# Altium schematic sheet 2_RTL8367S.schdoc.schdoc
size 431 x 309 mm; Symbol: Sheet-Symbol_A3; Device: Sheet-Symbol_A3; Company: 嘉立创EDA; Version: V1.0; Page Size: A3; @Project Name: RTL8367S_RTL8213B; @Page Count: 5; @Update Date: 2022-12-07; @Create Date: 2022-10-17; @Schematic Name: Schematic1; @Page No: 2; @Page Name: RTL8367S
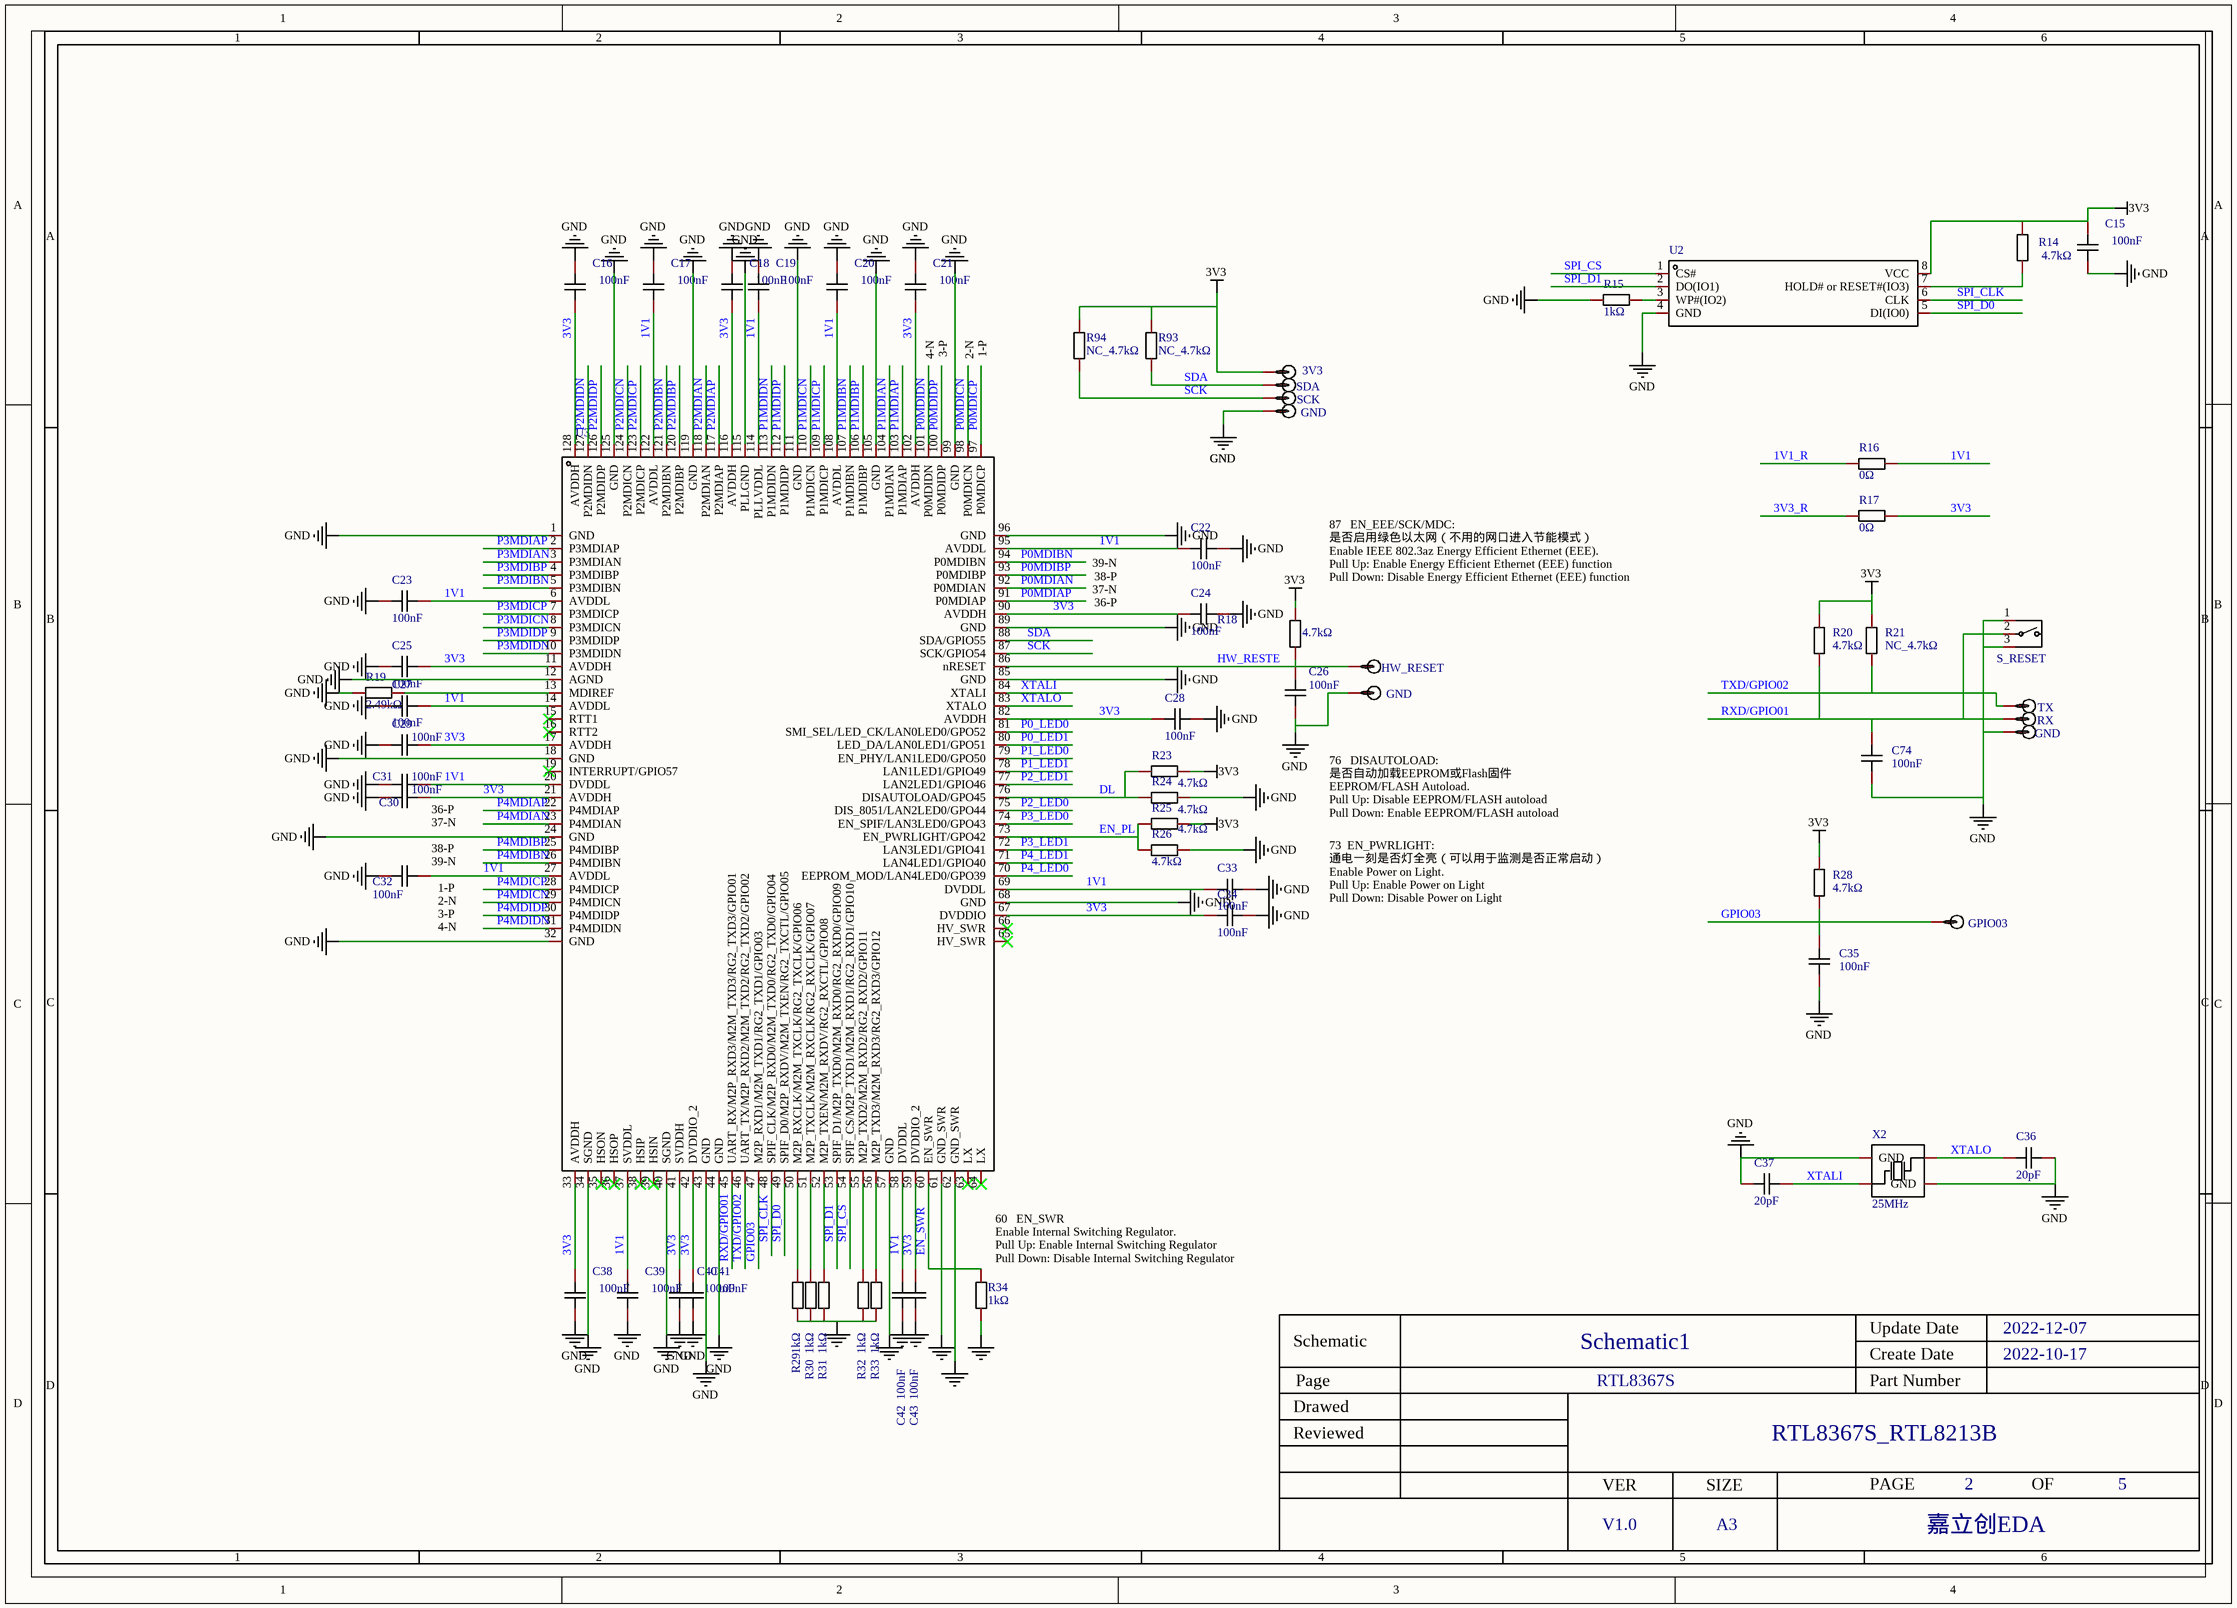
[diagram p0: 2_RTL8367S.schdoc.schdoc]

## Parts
(Parts that share a designator on the sheet are numbered #1, #2 ... from top to bottom, then left to right.)
3V3  测试点  [TP-1.5MM]  (value not drawn)
C15  value 100nF  [C0402_NEW]  (hidden comment: CL05B104KO5NNNC)
C16  value 100nF  [C0402_NEW]  (hidden comment: CL05B104KO5NNNC)
C17  value 100nF  [C0402_NEW]  (hidden comment: CL05B104KO5NNNC)
C18  value 100nF  [C0402_NEW]  (hidden comment: CL05B104KO5NNNC)
C19  value 100nF  [C0402_NEW]  (hidden comment: CL05B104KO5NNNC)
C20  value 100nF  [C0402_NEW]  (hidden comment: CL05B104KO5NNNC)
C21  value 100nF  [C0402_NEW]  (hidden comment: CL05B104KO5NNNC)
C22  value 100nF  [C0402_NEW]  (hidden comment: CL05B104KO5NNNC)
C23  value 100nF  [C0402_NEW]  (hidden comment: CL05B104KO5NNNC)
C24  value 100nF  [C0402_NEW]  (hidden comment: CL05B104KO5NNNC)
C25  value 100nF  [C0402_NEW]  (hidden comment: CL05B104KO5NNNC)
C26  value 100nF  [C0402_NEW]  (hidden comment: CL05B104KO5NNNC)
C27  value 100nF  [C0402_NEW]  (hidden comment: CL05B104KO5NNNC)
C28  value 100nF  [C0402_NEW]  (hidden comment: CL05B104KO5NNNC)
C29  value 100nF  [C0402_NEW]  (hidden comment: CL05B104KO5NNNC)
C30  value 100nF  [C0402_NEW]  (hidden comment: CL05B104KO5NNNC)
C31  value 100nF  [C0402_NEW]  (hidden comment: CL05B104KO5NNNC)
C32  value 100nF  [C0402_NEW]  (hidden comment: CL05B104KO5NNNC)
C33  value 100nF  [C0402_NEW]  (hidden comment: CL05B104KO5NNNC)
C34  value 100nF  [C0402_NEW]  (hidden comment: CL05B104KO5NNNC)
C35  value 100nF  [C0402_NEW]  (hidden comment: CL05B104KO5NNNC)
C36  value 20pF  [C0402]  (hidden comment: 0402CG200J500NT)
C37  value 20pF  [C0402]  (hidden comment: 0402CG200J500NT)
C38  value 100nF  [C0402_NEW]  (hidden comment: CL05B104KO5NNNC)
C39  value 100nF  [C0402_NEW]  (hidden comment: CL05B104KO5NNNC)
C40  value 100nF  [C0402_NEW]  (hidden comment: CL05B104KO5NNNC)
C41  value 100nF  [C0402_NEW]  (hidden comment: CL05B104KO5NNNC)
C42  value 100nF  [C0402_NEW]  (hidden comment: CL05B104KO5NNNC)
C43  value 100nF  [C0402_NEW]  (hidden comment: CL05B104KO5NNNC)
C74  value 100nF  [C0402_NEW]  (hidden comment: CL05B104KO5NNNC)
GND#1  测试点  [TP-1.5MM]  (value not drawn)
GND#2  测试点  [TP-1.5MM]  (value not drawn)
GND#3  测试点  [TP-1.5MM]  (value not drawn)
GPIO03  测试点  [TP-1.5MM]  (value not drawn)
HW_RESET  测试点  [TP-1.5MM]  (value not drawn)
R14  value 4.7kΩ  [R0402]  (hidden comment: 0402WGF4701TCE)
R15  value 1kΩ  [R0402]  (hidden comment: 0402WGF1001TCE)
R16  value 0Ω  [R0603]  (hidden comment: 0603WAF0000T5E)
R17  value 0Ω  [R0603]  (hidden comment: 0603WAF0000T5E)
R18  value 4.7kΩ  [R0402]  (hidden comment: 0402WGF4701TCE)
R19  value 2.49kΩ  [R0402]  (hidden comment: RC0402FR-072K49L)
R20  value 4.7kΩ  [R0402]  (hidden comment: 0402WGF4701TCE)
R21  value NC_4.7kΩ  [R0402]  (hidden comment: 0402WGF4701TCE)
R23  4.7kΩ  [R0402]
R24  value 4.7kΩ  [r0402]  (hidden comment: tr0402d10k0q1025z)
R25  4.7kΩ  [R0402]
R26  value 4.7kΩ  [r0402]  (hidden comment: tr0402d10k0q1025z)
R28  value 4.7kΩ  [R0402]  (hidden comment: 0402WGF4701TCE)
R29  value 1kΩ  [R0402]  (hidden comment: 0402WGF1001TCE)
R30  value 1kΩ  [R0402]  (hidden comment: 0402WGF1001TCE)
R31  value 1kΩ  [R0402]  (hidden comment: 0402WGF1001TCE)
R32  value 1kΩ  [R0402]  (hidden comment: 0402WGF1001TCE)
R33  value 1kΩ  [R0402]  (hidden comment: 0402WGF1001TCE)
R34  value 1kΩ  [R0402]  (hidden comment: 0402WGF1001TCE)
R93  value NC_4.7kΩ  [R0402]  (hidden comment: 0402WGF4701TCE)
R94  value NC_4.7kΩ  [R0402]  (hidden comment: 0402WGF4701TCE)
RX  测试点  [TP-1.5MM]  (value not drawn)
S_RESET  st-1133  [key-smd_st-1133]  (value not drawn)
SCK  测试点  [TP-1.5MM]  (value not drawn)
SDA  测试点  [TP-1.5MM]  (value not drawn)
TX  测试点  [TP-1.5MM]  (value not drawn)
U2  w25q32jvssiq  [soic-8_l5.3-w5.3-p1.27-ls8.0-bl]  (value not drawn)
U3  RTL8367S-CG  [LQFP-128_L14.0-W14.0-P0.40-LS16.0-BL]  (value not drawn)
X2  value 25MHz  [OSC-SMD_4P-L3.2-W2.5-BL]  (hidden comment: X322525MOB4SI)

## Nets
3V3: 3V3.1 C15.2 C16.1 C18.1 C21.1 C24.2 C25.2 C28.1 C29.2 C30.2 C34.1 C38.2 C40.2 C41.2 C43.2 R14.2 R17.2 R18.2 R20.2 R21.1 R23.2 R25.2 R28.2 R93.2 R94.2 U2.8(VCC) U3.11(AVDDH) U3.17(AVDDH) U3.21(AVDDH) U3.33(AVDDH) U3.41(SVDDH) U3.42(DVDDIO_2) U3.59(DVDDIO_2) U3.67(DVDDIO) U3.82(AVDDH) U3.90(AVDDH) U3.102(AVDDH) U3.116(AVDDH) U3.128(AVDDH)
GND: C15.1 C16.2 C17.2 C18.2 C19.2 C20.2 C21.2 C22.1 C23.1 C24.1 C25.1 C26.1 C27.1 C28.2 C29.1 C30.1 C31.1 C32.1 C33.2 C34.2 C35.1 C36.2 C37.1 C38.1 C39.1 C40.1 C41.1 C42.1 C43.1 C74.1 GND#1.1 GND#2.1 GND#3.1 R15.1 R19.1 R24.2 R26.2 R29.1 R30.1 R31.1 R32.1 R33.1 R34.1 S_RESET.1 S_RESET.3 U2.4(GND) U3.1(GND) U3.12(AGND) U3.18(GND) U3.24(GND) U3.32(GND) U3.34(SGND) U3.40(SGND) U3.43(GND) U3.44(GND) U3.57(GND) U3.61(GND_SWR) U3.62(GND_SWR) U3.68(GND) U3.85(GND) U3.89(GND) U3.96(GND) U3.99(GND) U3.105(GND) U3.111(GND) U3.115(PLLGND) U3.119(GND) U3.125(GND) X2.2(GND) X2.4(GND)
1V1: C17.1 C19.1 C20.1 C22.2 C23.2 C27.2 C31.2 C32.2 C33.1 C39.2 C42.2 R16.2 U3.6(AVDDL) U3.14(AVDDL) U3.20(DVDDL) U3.27(AVDDL) U3.37(SVDDL) U3.58(DVDDL) U3.69(DVDDL) U3.95(AVDDL) U3.108(AVDDL) U3.114(PLLVDDL) U3.122(AVDDL)
1V1_R: R16.1
3V3_R: R17.1
DL: R23.1 R24.1 U3.76(DISAUTOLOAD/GPO45)
EN_PL: R25.1 R26.1 U3.73(EN_PWRLIGHT/GPO42)
EN_SWR: R34.2 U3.60(EN_SWR)
GPIO03: C35.2 GPIO03.1 R28.1 U3.47(M2P_RXD1/M2M_TXD1/RG2_TXD1/GPIO03)
HW_RESTE: C26.2 HW_RESET.1 R18.1 U3.86(nRESET)
P0_LED0: U3.81(SMI_SEL/LED_CK/LAN0LED0/GPO52)
P0_LED1: U3.80(LED_DA/LAN0LED1/GPO51)
P0MDIAN: U3.92(P0MDIAN)
P0MDIAP: U3.91(P0MDIAP)
P0MDIBN: U3.94(P0MDIBN)
P0MDIBP: U3.93(P0MDIBP)
P0MDICN: U3.98(P0MDICN)
P0MDICP: U3.97(P0MDICP)
P0MDIDN: U3.101(P0MDIDN)
P0MDIDP: U3.100(P0MDIDP)
P1_LED0: U3.79(EN_PHY/LAN1LED0/GPO50)
P1_LED1: U3.78(LAN1LED1/GPIO49)
P1MDIAN: U3.104(P1MDIAN)
P1MDIAP: U3.103(P1MDIAP)
P1MDIBN: U3.107(P1MDIBN)
P1MDIBP: U3.106(P1MDIBP)
P1MDICN: U3.110(P1MDICN)
P1MDICP: U3.109(P1MDICP)
P1MDIDN: U3.113(P1MDIDN)
P1MDIDP: U3.112(P1MDIDP)
P2_LED0: U3.75(DIS_8051/LAN2LED0/GPO44)
P2_LED1: U3.77(LAN2LED1/GPIO46)
P2MDIAN: U3.118(P2MDIAN)
P2MDIAP: U3.117(P2MDIAP)
P2MDIBN: U3.121(P2MDIBN)
P2MDIBP: U3.120(P2MDIBP)
P2MDICN: U3.124(P2MDICN)
P2MDICP: U3.123(P2MDICP)
P2MDIDN: U3.127(P2MDIDN)
P2MDIDP: U3.126(P2MDIDP)
P3_LED0: U3.74(EN_SPIF/LAN3LED0/GPO43)
P3_LED1: U3.72(LAN3LED1/GPIO41)
P3MDIAN: U3.3(P3MDIAN)
P3MDIAP: U3.2(P3MDIAP)
P3MDIBN: U3.5(P3MDIBN)
P3MDIBP: U3.4(P3MDIBP)
P3MDICN: U3.8(P3MDICN)
P3MDICP: U3.7(P3MDICP)
P3MDIDN: U3.10(P3MDIDN)
P3MDIDP: U3.9(P3MDIDP)
P4_LED0: U3.70(EEPROM_MOD/LAN4LED0/GPO39)
P4_LED1: U3.71(LAN4LED1/GPIO40)
P4MDIAN: U3.23(P4MDIAN)
P4MDIAP: U3.22(P4MDIAP)
P4MDIBN: U3.26(P4MDIBN)
P4MDIBP: U3.25(P4MDIBP)
P4MDICN: U3.29(P4MDICN)
P4MDICP: U3.28(P4MDICP)
P4MDIDN: U3.31(P4MDIDN)
P4MDIDP: U3.30(P4MDIDP)
RXD/GPIO01: C74.2 R20.1 RX.1 S_RESET.2 U3.45(UART_RX/M2P_RXD3/M2M_TXD3/RG2_TXD3/GPIO01)
SCK: R94.1 SCK.1 U3.87(SCK/GPIO54)
SDA: R93.1 SDA.1 U3.88(SDA/GPIO55)
SPI_CLK: U2.6(CLK) U3.48(SPIF_CLK/M2P_RXD0/M2M_TXD0/RG2_TXD0/GPIO04)
SPI_CS: U2.1(CS#) U3.54(SPIF_CS/M2P_TXD1/M2M_RXD1/RG2_RXD1/GPIO10)
SPI_D0: U2.5(DI(IO0)) U3.49(SPIF_D0/M2P_RXDV/M2M_TXEN/RG2_TXCTL/GPIO05)
SPI_D1: U2.2(DO(IO1)) U3.53(SPIF_D1/M2P_TXD0/M2M_RXD0/RG2_RXD0/GPIO09)
TXD/GPIO02: R21.2 TX.1 U3.46(UART_TX/M2P_RXD2/M2M_TXD2/RG2_TXD2/GPIO02)
XTALI: C37.2 U3.84(XTALI) X2.1(OSC1)
XTALO: C36.1 U3.83(XTALO) X2.3(OSC2)
NetR14_1: R14.1 U2.7(HOLD#_or_RESET#(IO3))
NetR15_2: R15.2 U2.3(WP#(IO2))
NetR19_2: R19.2 U3.13(MDIREF)
NetR29_2: R29.2 U3.50(M2P_RXCLK/M2M_TXCLK/RG2_TXCLK/GPIO06)
NetR30_2: R30.2 U3.51(M2P_TXCLK/M2M_RXCLK/RG2_RXCLK/GPIO07)
NetR31_2: R31.2 U3.52(M2P_TXEN/M2M_RXDV/RG2_RXCTL/GPIO08)
NetR32_2: R32.2 U3.55(M2P_TXD2/M2M_RXD2/RG2_RXD2/GPIO11)
NetR33_2: R33.2 U3.56(M2P_TXD3/M2M_RXD3/RG2_RXD3/GPIO12)

Not connected (* = marked no-connect by the designer): U3 15(RTT1)* 16(RTT2)* 19(INTERRUPT/GPIO57)* 35(HSON)* 36(HSOP)* 38(HSIP)* 39(HSIN)* 63(LX)* 64(LX)* 65(HV_SWR)* 66(HV_SWR)*

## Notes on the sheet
- (near C21) 4-N
- (near C21) 3-P
- 2-N
- 1-P
- 87   EN_EEE/SCK/MDC:
  是否启用绿色以太网（不用的网口进入节能模式）
  Enable IEEE 802.3az Energy Efficient Ethernet (EEE).
  Pull Up: Enable Energy Efficient Ethernet (EEE) function
  Pull Down: Disable Energy Efficient Ethernet (EEE) function
- 37-N
- 38-P
- 39-N
- 36-P
- 76   DISAUTOLOAD:
  是否自动加载EEPROM或Flash固件
  EEPROM/FLASH Autoload.
  Pull Up: Disable EEPROM/FLASH autoload
  Pull Down: Enable EEPROM/FLASH autoload
- 73  EN_PWRLIGHT:
  通电一刻是否灯全亮（可以用于监测是否正常启动）
  Enable Power on Light.
  Pull Up: Enable Power on Light
  Pull Down: Disable Power on Light
- (near C32) 38-P
- (near C32) 39-N
- (near C32) 2-N
- (near C32) 1-P
- (near C32) 4-N
- (near C32) 3-P
- (near R34) 60   EN_SWR
  Enable Internal Switching Regulator.
  Pull Up: Enable Internal Switching Regulator
  Pull Down: Disable Internal Switching Regulator

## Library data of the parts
3V3 GND#1-GND#3 HW_RESET RX SCK SDA TX = 测试点: Add into BOM: no; Convert to PCB: yes
C15-C35 C38-C43 C74 = CL05B104KO5NNNC: 容值:100nF;精度:±10%;额定电压:25V;温度系数:X7R;; Manufacturer: SAMSUNG(三星); Symbol: fn15x104k250png; Add into BOM: yes; Tolerance: ±10%; Voltage Rated: 16V; Temperature Coefficient: X7R
C36 C37 = 0402CG200J500NT: 容值:100nF;精度:±10%;额定电压:25V;温度系数:X7R;; Manufacturer: FH(风华); Symbol: fn15x104k250png; Add into BOM: yes; Tolerance: ±5%; Voltage Rated: 50V; Temperature Coefficient: C0G
GPIO03 = 测试点: Add into BOM: yes; Check: false
R14 R18 R28 = 0402WGF4701TCE: 电阻类型:薄膜电阻;阻值:10kΩ;精度:±0.5%;功率:63mW;温度系数:±25ppm/;最大工作电压:25V;工作温度范围:-55~+155;; Manufacturer: UNI-ROYAL(厚声); Symbol: tr0402d10kq1025; Add into BOM: yes; Tolerance: ±1%; Power(Watts): 1/16W; Temperature Coefficient: ±100ppm/℃; Overload Voltage (Max): 50V
R15 R29-R34 = 0402WGF1001TCE: 电阻类型:薄膜电阻;阻值:10kΩ;精度:±0.5%;功率:63mW;温度系数:±25ppm/;最大工作电压:25V;工作温度范围:-55~+155;; Manufacturer: UNI-ROYAL(厚声); Symbol: tr0402d10kq1025; Add into BOM: yes; Tolerance: ±1%; Power(Watts): 62.5mW; Temperature Coefficient: ±100ppm/℃; Overload Voltage (Max): 50V
R16 R17 = 0603WAF0000T5E: Manufacturer: UNI-ROYAL(厚声); Symbol: 电阻; Add into BOM: yes; Tolerance: ±1%; Power(Watts): 1/10W; Overload Voltage (Max): 75V; Description: 温度系数:-;精度:±1%;阻值:0Ω;功率:1/10W;最大工作电压:75V;工作温度范围:-55℃~+155℃;
R19 = RC0402FR-072K49L: 电阻类型:薄膜电阻;阻值:10kΩ;精度:±0.5%;功率:63mW;温度系数:±25ppm/;最大工作电压:25V;工作温度范围:-55~+155;; Manufacturer: YAGEO(国巨); Symbol: tr0402d10kq1025; Add into BOM: yes; Power(Watts): 1/16W; Tolerance: ±1%; Temperature Coefficient: ±100ppm/℃; Overload Voltage (Max): 50V
R20 R21 R93 R94 = 0402WGF4701TCE: 电阻类型:薄膜电阻;阻值:10kΩ;精度:±0.5%;功率:63mW;温度系数:±25ppm/;最大工作电压:25V;工作温度范围:-55~+155;; Manufacturer: UNI-ROYAL(厚声); Symbol: tr0402d10kq1025; Add into BOM: no; Convert to PCB: yes; Tolerance: ±1%; Power(Watts): 1/16W; Temperature Coefficient: ±100ppm/℃; Overload Voltage (Max): 50V
R23 = 0402WGF4701TCE: 电阻类型:厚膜电阻;阻值:4.7kΩ;精度:±1%;功率:62.5mW;温度系数:±100ppm/℃;最大工作电压:50V;工作温度范围:-55℃~+155℃;; Manufacturer: UNI-ROYAL(厚声); Symbol: tr0402d10kq1025; Add into BOM: no; Convert to PCB: yes; Tolerance: ±1%; Power(Watts): 1/16W; Overload Voltage (Max): 50V
R24 = tr0402d10k0q1025z: 电阻类型:薄膜电阻;阻值:10kΩ;精度:±0.5%;功率:63mW;温度系数:±25ppm/;最大工作电压:25V;工作温度范围:-55~+155;; Manufacturer: EVER OHMS(天二科技); Symbol: tr0402d10kq1025; Add into BOM: yes; Tolerance: ±0.5%; Power(Watts): 63mW; Temperature Coefficient: ±25ppm/; Overload Voltage (Max): 25V
R25 = 0402WGF4701TCE: 电阻类型:厚膜电阻;阻值:4.7kΩ;精度:±1%;功率:62.5mW;温度系数:±100ppm/℃;最大工作电压:50V;工作温度范围:-55℃~+155℃;; Manufacturer: UNI-ROYAL(厚声); Symbol: tr0402d10kq1025; Add into BOM: yes; Tolerance: ±1%; Power(Watts): 1/16W; Overload Voltage (Max): 50V
R26 = tr0402d10k0q1025z: 电阻类型:薄膜电阻;阻值:10kΩ;精度:±0.5%;功率:63mW;温度系数:±25ppm/;最大工作电压:25V;工作温度范围:-55~+155;; Manufacturer: EVER OHMS(天二科技); Symbol: tr0402d10kq1025; Add into BOM: no; Convert to PCB: yes; Tolerance: ±0.5%; Power(Watts): 63mW; Temperature Coefficient: ±25ppm/; Overload Voltage (Max): 25V
S_RESET = st-1133: Manufacturer: RISHENG(日昇); Add into BOM: no; Convert to PCB: yes; Contact Current: 50mA; Voltage Rating (DC): 12V; Insulation Resistance: 100MΩ; Circuit: 单刀单掷; Actuator Style: 圆形按钮; Actuator/Cap Color: 白色; Operating Force: 180gf@±50gf; Mechanical Life: 100000; Pin Style: SMD接片; Switch Length: 4.5mm; Switch Width: 3.4mm; Description: 触点电流:50mA;额定电压(DC):12V;绝缘电阻:100MΩ;电路结构:单刀单掷;安装方式:卧贴;按钮形状:圆形按钮;按钮/盖帽颜色:白色;作用力:180gf@±50gf;机械寿命:100000;工作温度:-20℃~+85℃;引脚样式:SMD接片;开关长度:4.5mm;开关宽度:3.4mm;
U2 = w25q32jvssiq: Manufacturer: WINBOND(华邦); Symbol: w25q32jvssiq_c179173; Add into BOM: no; Convert to PCB: yes; Description: 存储器类型:-;存储器构架(格式):-;技术:-;存储器容量:-;时钟频率:-;存储器接口类型:-;
U3 = RTL8367S-CG: Manufacturer: REALTEK(瑞昱); Add into BOM: yes; Description: 类型:-;标准:-;接口类型:-;电源电压:-;
X2 = X322525MOB4SI: 晶振类型:-;频率:-;频率公差:-;频率稳定度:-;负载电容:-;工作温度:-;; Manufacturer: YXC(扬兴晶振); Symbol: 7e25000e20ucg; Add into BOM: yes; Crystal Type: 贴片无源晶振; Frequency Tolerance: ±10ppm; Frequency Stability: ±30ppm; Load Capacitance: 12pF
